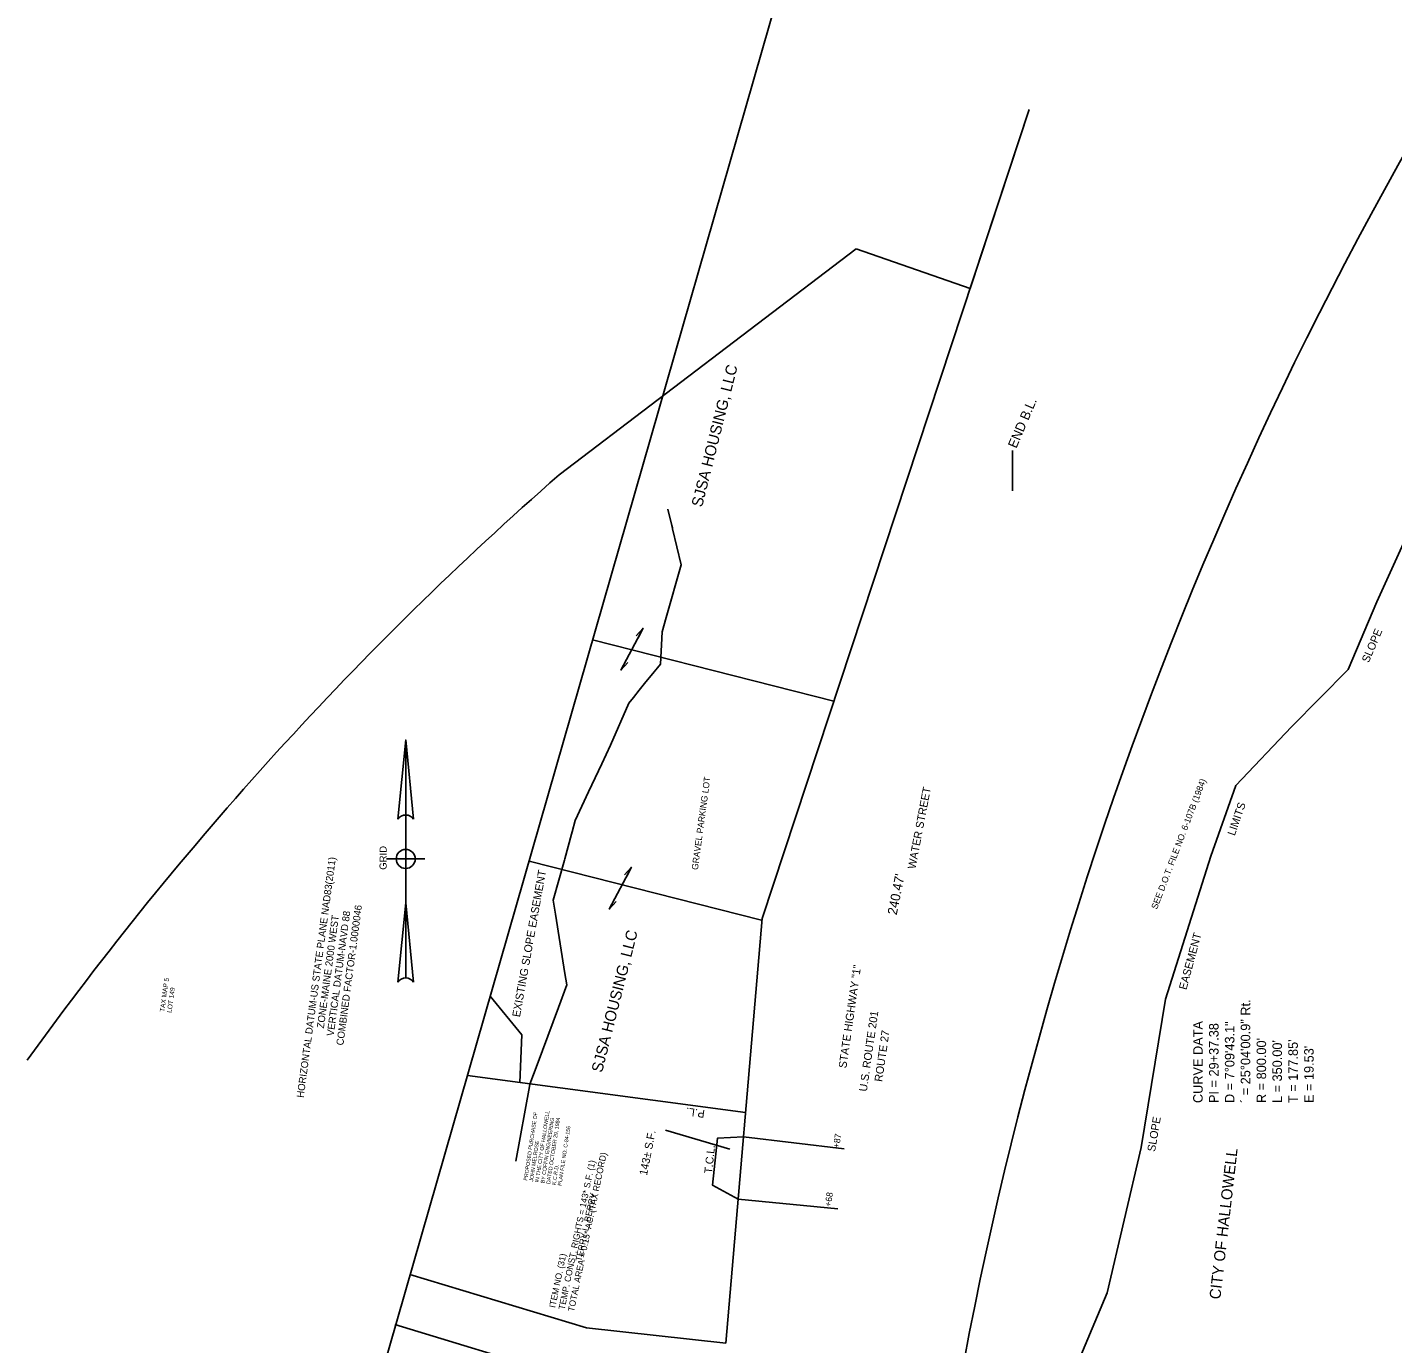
# Model space of a CAD drawing. Extents: x 1133267 to 1139526, y 528613 to 531538.
# Drawn here: x 1137213 to 1137643.6, y 530679.9 to 531094.9 of the extents above; entities that cross this region are included whole.
import ezdxf

# ---------------------------------------------------------------- set-up
doc = ezdxf.new("R2010")
doc.units = 0
for name, color, linetype in [('BASELN DIST_NTES', 7, 'Continuous'), ('D_Roadway_Centerline_CurveData', 7, 'Continuous'), ('E_Property_Easement_Line', 7, 'Continuous'), ('E_Property_Line', 7, 'Continuous'), ('E_Property_LotLine', 7, 'Continuous'), ('E_ROW_Line', 7, 'Continuous'), ('E_ROW_Railroad', 7, 'Continuous'), ('MISCELLN TEXT', 7, 'Continuous'), ('North Arrows', 7, 'Continuous'), ('P_Ease_Temp_Grading_Line', 7, 'Continuous'), ('P_ROW_Tie_Lines', 7, 'Continuous'), ('PROPERTY NOTES', 7, 'Continuous'), ('PRP OWNER NAMES', 7, 'Continuous'), ('PRPTY SETUPS', 7, 'Continuous'), ('ROW REFERENCES', 7, 'Continuous'), ('S_Annotation_Label', 7, 'Continuous'), ('S_Trees_TreeLine', 7, 'Continuous'), ('TEMP RIGHTS', 7, 'Continuous'), ('Temp Rights Text', 7, 'Continuous'), ('TIE STATIONS', 7, 'Continuous')]:
    doc.layers.add(name, color=color, linetype=linetype)

msp = doc.modelspace()

# ---------------------------------------------------------------- linework, layer by layer
at = {"layer": 'E_Property_Easement_Line'}
for p, q in [((1137638.57, 530913.8), (1137657.78, 530956.11)), ((1137629.59, 530892.38), (1137638.57, 530913.8)), ((1137611.71, 530874.37), (1137629.59, 530892.38)), ((1137594.11, 530855.83), (1137611.71, 530874.37)), ((1137586.28, 530833.54), (1137594.11, 530855.83)), ((1137571.94, 530788.52), (1137586.28, 530833.54)), ((1137358.98, 530789.45), (1137368.99, 530777.21)), ((1137564.22, 530741.73), (1137571.94, 530788.52)), ((1137368.99, 530777.21), (1137368.37, 530762.25)), ((1137553.5, 530695.92), (1137564.22, 530741.73)), ((1137534.74, 530651.42), (1137553.5, 530695.92))]:
    msp.add_line(p, q, dxfattribs=at)
at = {"layer": 'E_Property_Line'}
for p, q in [((1137400.21, 530892.23), (1137407.18, 530905.42)), ((1137396.53, 530816.88), (1137403.5, 530830.07)), ((1137351.8, 530764.46), (1137439.48, 530752.76))]:
    msp.add_line(p, q, dxfattribs=at)
for points in [[(1137405.03, 530903.02), (1137407.18, 530905.42), (1137407.18, 530905.42), (1137405.72, 530902.66)], [(1137402.36, 530894.63), (1137400.21, 530892.23), (1137400.21, 530892.23), (1137401.67, 530894.99)], [(1137401.35, 530827.68), (1137403.5, 530830.07), (1137403.5, 530830.07), (1137402.04, 530827.31)], [(1137398.68, 530819.28), (1137396.53, 530816.88), (1137396.53, 530816.88), (1137397.99, 530819.65)]]:
    msp.add_lwpolyline(points, dxfattribs=at)
at = {"layer": 'E_Property_LotLine'}
msp.add_line((1137444.53, 530813.39), (1137371.22, 530832.01), dxfattribs=at)
msp.add_lwpolyline([(1137467.36, 530882.49), (1137391.29, 530901.81)], dxfattribs=at)
at = {"layer": 'E_ROW_Line'}
for p, q in [((1137312.59, 530628.06), (1137494.87, 531262.1)), ((1137389.36, 530684.86), (1137333.67, 530701.74)), ((1137386.04, 530668.63), (1137328.88, 530685.95)), ((1137433.29, 530680.06), (1137389.36, 530684.86))]:
    msp.add_line(p, q, dxfattribs=at)
msp.add_lwpolyline([(1137433.29, 530680.06), (1137444.7, 530813.9), (1137528.98, 531068.94)], dxfattribs=at)
msp.add_arc((1138725.38, 530445.92), 1238.24, 148.69617, 174.64451, dxfattribs=at)
at = {"layer": 'E_ROW_Railroad'}
for p, q in [((1137510.34, 531012.58), (1137528.98, 531068.94)), ((1137380.76, 530953.84), (1137474.42, 531025.02)), ((1137474.42, 531025.02), (1137510.34, 531012.58))]:
    msp.add_line(p, q, dxfattribs=at)
msp.add_arc((1138105.41, 530126.66), 1099.7, 131.21977, 144.24222, dxfattribs=at)
at = {"layer": 'North Arrows'}
for p, q in [((1137329.83, 530845.21), (1137332.33, 530870.21)), ((1137332.33, 530870.21), (1137332.33, 530795.21)), ((1137332.33, 530870.21), (1137334.83, 530845.21)), ((1137326.33, 530832.71), (1137338.33, 530832.71)), ((1137329.83, 530793.87), (1137332.33, 530818.87)), ((1137332.33, 530818.87), (1137334.83, 530793.87))]:
    msp.add_line(p, q, dxfattribs=at)
for points in [[(1137332.33, 530846.55), (1137332.33, 530870.21), (1137329.83, 530845.21)], [(1137334.83, 530845.21), (1137332.33, 530870.21), (1137332.33, 530846.55)], [(1137332.33, 530829.71), (1137332.33, 530832.71), (1137329.33, 530832.71)], [(1137332.33, 530835.71), (1137332.33, 530832.71), (1137335.33, 530832.71)], [(1137332.33, 530795.21), (1137332.33, 530818.87), (1137329.83, 530793.87)], [(1137334.83, 530793.87), (1137332.33, 530818.87), (1137332.33, 530795.21)]]:
    msp.add_lwpolyline(points, dxfattribs=at)
msp.add_circle((1137332.33, 530832.71), 3, dxfattribs=at)
for centre, start, end in [((1137332.33, 530843.55), 33.5573, 146.4427), ((1137332.33, 530843.55), 90, 146.4427), ((1137332.33, 530843.55), 33.5573, 90), ((1137332.33, 530832.71), 180, 270), ((1137332.33, 530832.71), 0, 90), ((1137332.33, 530792.21), 33.5573, 146.4427), ((1137332.33, 530792.21), 90, 146.4427), ((1137332.33, 530792.21), 33.5573, 90)]:
    msp.add_arc(centre, 3, start, end, dxfattribs=at)
at = {"layer": 'P_Ease_Temp_Grading_Line'}
msp.add_lwpolyline([(1137438.83, 530745.13), (1137430.71, 530744.69), (1137429.09, 530729.85), (1137437.16, 530725.44)], dxfattribs=at)
at = {"layer": 'P_ROW_Tie_Lines'}
for p, q in [((1137523.66, 530961.51), (1137523.66, 530948.74)), ((1137470.62, 530741.31), (1137438.83, 530745.13))]:
    msp.add_line(p, q, dxfattribs=at)
at = {"layer": 'S_Trees_TreeLine'}
msp.add_lwpolyline([(1137415.02, 530942.93), (1137416.25, 530937.84), (1137416.42, 530937.14), (1137416.51, 530936.74), (1137419.25, 530925.44), (1137414.51, 530908.83), (1137413.21, 530904.3), (1137412.65, 530894.08), (1137411.71, 530892.92), (1137410.71, 530891.7), (1137407.68, 530887.98), (1137405.99, 530885.9), (1137404.15, 530883.64), (1137402.67, 530881.82), (1137396.93, 530868.6), (1137394.15, 530862.64), (1137390.02, 530853.83), (1137385.82, 530844.86), (1137384.83, 530841.26), (1137384.64, 530840.56), (1137382.5, 530832.79), (1137382.38, 530832.36), (1137378.89, 530819.68), (1137379.59, 530815.3), (1137382.57, 530796.57), (1137383.13, 530793.03), (1137380.47, 530785.87), (1137373.75, 530767.79), (1137371.49, 530761.7), (1137371.34, 530760.92), (1137367.04, 530737.47)], dxfattribs=at)
at = {"layer": 'Temp Rights Text'}
msp.add_line((1137414.28, 530747.2), (1137434.56, 530741.2), dxfattribs=at)
at = {"layer": 'TIE STATIONS'}
msp.add_line((1137468.57, 530722.42), (1137437.16, 530725.44), dxfattribs=at)

# ---------------------------------------------------------------- texts
at = {"layer": 'BASELN DIST_NTES'}
for s, rotation, p in [('END B.L.', 66.905, (1137524.89, 530961.95)), ("240.47'", 78.6993, (1137487.16, 530814.87))]:
    msp.add_text(s, height=3, rotation=rotation, dxfattribs=at).set_placement(p)
at = {"layer": 'D_Roadway_Centerline_CurveData'}
for s, p in [('´ = 25%%d04\'00.9" Rt.', (1137598.67, 530755.75)), ('CURVE DATA', (1137583.67, 530755.75)), ('PI = 29+37.38', (1137588.67, 530755.75)), ('D = 7%%d09\'43.1"', (1137593.67, 530755.75)), ("R = 800.00'", (1137603.67, 530755.75)), ("L = 350.00'", (1137608.67, 530755.75)), ("T = 177.85'", (1137613.67, 530755.75)), ("E = 19.53'", (1137618.67, 530755.75))]:
    msp.add_text(s, height=3, rotation=90, dxfattribs=at).set_placement(p)
at = {"layer": 'E_Property_Line'}
msp.add_text('P.L.', height=2.5, rotation=172.498, dxfattribs=at).set_placement((1137426.78, 530753.53))
at = {"layer": 'E_ROW_Line'}
for s, rotation, p in [('SLOPE', 66.912, (1137636.01, 530894.37)), ('LIMITS', 70.903, (1137593.77, 530839.85)), ('EXISTING SLOPE EASEMENT', 79.8494, (1137368.35, 530782.71)), ('EASEMENT', 74.9951, (1137578.53, 530791.28)), ('SLOPE', 80.3892, (1137568.63, 530740.28))]:
    msp.add_text(s, height=2.5, rotation=rotation, dxfattribs=at).set_placement(p)
at = {"layer": 'MISCELLN TEXT'}
for s, rotation, p in [('WATER STREET', 79.1707, (1137493.06, 530829.39)), ('STATE HIGHWAY "1"', 81.8026, (1137471.29, 530766.61)), ('U.S. ROUTE 201', 81.8026, (1137477.75, 530759.25)), ('ROUTE 27', 81.8026, (1137482.6, 530762.33))]:
    msp.add_text(s, height=2.5, rotation=rotation, dxfattribs=at).set_placement(p)
at = {"layer": 'North Arrows'}
for s, height, rotation, p in [('GRID', 2.249, 90, (1137326.33, 530829.29)), ('HORIZONTAL DATUM-US STATE PLANE NAD83(2011)', 2.2488, 82.3779, (1137300.17, 530757.31)), ('ZONE-MAINE 2000 WEST', 2.2488, 82.3779, (1137306.52, 530779.19)), ('VERTICAL DATUM-NAVD 88', 2.2488, 82.3779, (1137309.62, 530776.76)), ('COMBINED FACTOR-1.0000046', 2.2488, 82.3779, (1137312.65, 530773.81))]:
    msp.add_text(s, height=height, rotation=rotation, dxfattribs=at).set_placement(p)
at = {"layer": 'PROPERTY NOTES'}
for s, height, rotation, p in [('TAX MAP 5', 1.5, 82.2782, (1137256.26, 530784.41)), ('LOT 149', 1.5, 82.2782, (1137258.5, 530784.11)), ('PROPOSED PURCHASE OF', 1.2, 81.3853, (1137370.69, 530731.22)), ('IN THE CITY OF HALLOWELL', 1.2, 81.3853, (1137374.28, 530730.67)), ('BY COFFIN ENGINEERING', 1.2, 81.3853, (1137376.07, 530730.4)), ('DATED OCTOBER 29, 1984', 1.2, 81.3853, (1137377.86, 530730.13)), ('PLAN FILE NO. C-84-156', 1.2, 81.3853, (1137381.44, 530729.59)), ('JOHN MELROSE', 1.2, 81.3853, (1137372.48, 530730.94)), ('K.C.R.D.', 1.2, 81.3853, (1137379.65, 530729.86))]:
    msp.add_text(s, height=height, rotation=rotation, dxfattribs=at).set_placement(p)
at = {"layer": 'PRP OWNER NAMES'}
for s, height, rotation, p in [('SJSA HOUSING, LLC', 3.5, 75.8089, (1137425.77, 530943.41)), ('SJSA HOUSING, LLC', 3.5, 75.8089, (1137394.25, 530765.16)), ('CITY OF HALLOWELL', 3.5, 83.4344, (1137589.22, 530693.74)), ('TERRY L. BERRY', 2, 77.7127, (1137387.8, 530705.7))]:
    msp.add_text(s, height=height, rotation=rotation, dxfattribs=at).set_placement(p)
at = {"layer": 'PRPTY SETUPS'}
for s, p in [('TEMP. CONST. RIGHTS = 143* S.F. (1)', (1137382.45, 530690.45)), ('TOTAL AREA = 0.15* AC. (TAX RECORD)', (1137385.41, 530689.84)), ('ITEM NO. (31)', (1137379.49, 530691.06))]:
    msp.add_text(s, height=2, rotation=78.3348, dxfattribs=at).set_placement(p)
at = {"layer": 'ROW REFERENCES'}
msp.add_text('SEE D.O.T. FILE NO. 6-107B (1984)', height=2, rotation=69.1694, dxfattribs=at).set_placement((1137569.25, 530816.68))
at = {"layer": 'S_Annotation_Label'}
msp.add_text('GRAVEL PARKING LOT', height=2, rotation=82.2974, dxfattribs=at).set_placement((1137424.46, 530829.16))
at = {"layer": 'TEMP RIGHTS'}
msp.add_text('T.C.L.', height=2.49, rotation=83.7695, dxfattribs=at).set_placement((1137428.94, 530733.41))
at = {"layer": 'Temp Rights Text'}
msp.add_text('143± S.F.', height=2.49, rotation=78.9138, dxfattribs=at).set_placement((1137408.42, 530732.8))
at = {"layer": 'TIE STATIONS'}
for s, p in [('+87', (1137469.02, 530741.43)), ('+68', (1137466.41, 530722.98))]:
    msp.add_text(s, height=2.01, rotation=81.2624, dxfattribs=at).set_placement(p)

doc.saveas('drawing.dxf')
